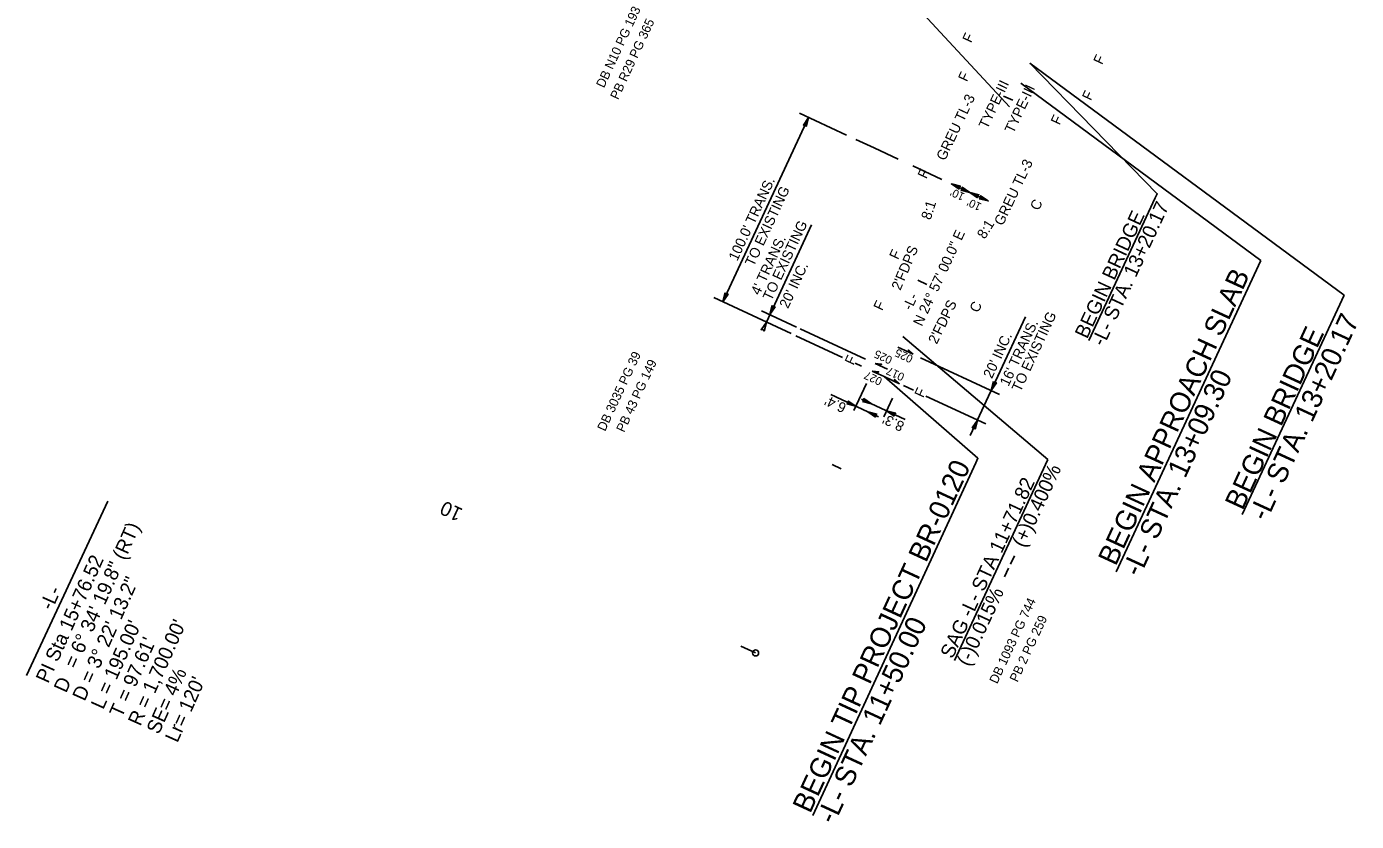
# Model space of a CAD drawing. Extents: x 2532362 to 2533150, y 715234 to 716115.
# Drawn here: x 2532362 to 2533016, y 715234 to 715625 of the extents above; entities that cross this region are included whole.
import ezdxf

# ---------------------------------------------------------------- set-up
doc = ezdxf.new("R2010")
doc.units = 0
for name, color, linetype in [('Default', 7, 'Continuous'), ('Exist Property Deed Book Text', 7, 'Continuous'), ('Old_Level_1', 7, 'Continuous'), ('Prop Dimension', 7, 'Continuous'), ('Prop Dimension Text', 7, 'Continuous'), ('Prop DSN Text', 7, 'Continuous'), ('Prop Horizontal Alignment Curve and Spiral Data', 7, 'Continuous'), ('Prop Horizontal Alignment Direction Label', 7, 'Continuous'), ('Prop Horizontal Alignment Station Label', 7, 'Continuous'), ('Prop Horizontal Alignment Tick Label', 7, 'Continuous'), ('Prop Horizontal Alignment Tick Large', 7, 'Continuous'), ('Prop Horizontal Alignment Tick Small', 7, 'Continuous'), ('Prop Plan Preparation Crest Label', 7, 'Continuous'), ('Prop Plan Preparation Sag Label', 7, 'Continuous'), ('Scratch_Level_0', 7, 'Continuous')]:
    doc.layers.add(name, color=color, linetype=linetype)

msp = doc.modelspace()

# ---------------------------------------------------------------- linework, layer by layer
at = {"layer": 'Old_Level_1'}
for points in [[(2533010.47, 715493), (2532855.87, 715607.16)], [(2532969.52, 715509.99), (2532851.29, 715597.3)], [(2532898.24, 715356.78), (2532969.52, 715509.99)], [(2532960.2, 715384.93), (2533010.47, 715493)]]:
    msp.add_lwpolyline(points, dxfattribs=at)
at = {"layer": 'Prop Dimension'}
for p, q in [((2532704.72, 715489.71), (2532746.93, 715580.45)), ((2532765.6, 715571.76), (2532742.49, 715582.51)), ((2532779.27, 715565.4), (2532770.14, 715569.65)), ((2532790.96, 715559.96), (2532779.27, 715565.4)), ((2532812.48, 715549.95), (2532798.22, 715556.58)), ((2532826.27, 715543.53), (2532817.21, 715547.75)), ((2532835.34, 715539.31), (2532826.27, 715543.53)), ((2532726.15, 715479.74), (2532748.41, 715527.58)), ((2532738.27, 715474.1), (2532700.27, 715491.78)), ((2532740.99, 715477.25), (2532723.76, 715485.26)), ((2532826.43, 715423.81), (2532853.66, 715482.33)), ((2532774.94, 715461.45), (2532742.81, 715476.4)), ((2532763.67, 715462.29), (2532740.67, 715472.99)), ((2532840.84, 715444.11), (2532802.05, 715462.16)), ((2532772.93, 715457.98), (2532769.77, 715459.45)), ((2532775.47, 715449.5), (2532769.25, 715436.13)), ((2532781.36, 715433.09), (2532757.81, 715444.04)), ((2532788.22, 715442.17), (2532783.98, 715433.06)), ((2532798.52, 715446.15), (2532793.62, 715448.42)), ((2532834.09, 715429.6), (2532804.66, 715443.29)), ((2532772.96, 715441.79), (2532794.5, 715431.77))]:
    msp.add_line(p, q, dxfattribs=at)
for points in [[(2532745.81, 715576.02), (2532746.93, 715580.45), (2532744.36, 715576.64), (2532745.32, 715576.84)], [(2532820.96, 715545.15), (2532817.21, 715547.75), (2532821.65, 715546.57), (2532820.79, 715546.08)], [(2532821.85, 715544.65), (2532826.27, 715543.53), (2532822.46, 715546.1), (2532822.66, 715545.14)], [(2532830.03, 715540.93), (2532826.27, 715543.53), (2532830.71, 715542.35), (2532829.85, 715541.86)], [(2532830.91, 715540.43), (2532835.34, 715539.31), (2532831.53, 715541.88), (2532831.73, 715540.92)], [(2532705.84, 715494.14), (2532704.72, 715489.71), (2532707.29, 715493.52), (2532706.32, 715493.32)], [(2532728.96, 715487.79), (2532727.84, 715483.37), (2532730.41, 715487.18), (2532729.44, 715486.98)], [(2532725.03, 715475.31), (2532726.15, 715479.74), (2532723.58, 715475.93), (2532724.54, 715476.13)], [(2532798.42, 715463.84), (2532796.13, 715466.01), (2532796.33, 715464.82)], [(2532778.29, 715455.56), (2532781.44, 715455.23), (2532780.4, 715454.6)], [(2532779.7, 715459.32), (2532782.85, 715458.98), (2532781.81, 715458.36)], [(2532791.58, 715449.38), (2532789.28, 715451.55), (2532789.48, 715450.36)], [(2532837.88, 715450.44), (2532836.76, 715446.01), (2532839.33, 715449.82), (2532838.37, 715449.62)], [(2532773.43, 715440.63), (2532777.85, 715439.51), (2532774.05, 715442.08), (2532774.25, 715441.11)], [(2532765.82, 715439.38), (2532770.24, 715438.26), (2532766.43, 715440.83), (2532766.63, 715439.87)], [(2532779.79, 715432.96), (2532776.04, 715435.56), (2532780.48, 715434.38), (2532779.62, 715433.89)], [(2532789.1, 715433.43), (2532785.34, 715436.03), (2532789.78, 715434.84), (2532788.92, 715434.36)], [(2532828.89, 715427.07), (2532830.01, 715431.5), (2532827.44, 715427.69), (2532828.4, 715427.89)]]:
    msp.add_lwpolyline(points, close=True, dxfattribs=at)
at = {"layer": 'Prop Dimension Text'}
for p, q in [((2532798.42, 715463.84), (2532790.84, 715467.37)), ((2532784.09, 715452.86), (2532778.29, 715455.56)), ((2532785.78, 715456.49), (2532779.7, 715459.32)), ((2532791.58, 715449.38), (2532784.09, 715452.86))]:
    msp.add_line(p, q, dxfattribs=at)
at = {"layer": 'Prop DSN Text'}
msp.add_line((2532829.19, 715410.36), (2532749.07, 715236.8), dxfattribs=at)
msp.add_lwpolyline([(2532829.19, 715410.36), (2532830.27, 715412.69), (2532784.09, 715452.86)], dxfattribs=at)
at = {"layer": 'Prop Horizontal Alignment Direction Label'}
msp.add_line((2532362.11, 715305.81), (2532402.04, 715391.62), dxfattribs=at)
at = {"layer": 'Prop Horizontal Alignment Station Label'}
msp.add_circle((2532720.82, 715316.86), 1.5, dxfattribs=at)
at = {"layer": 'Prop Horizontal Alignment Tick Large'}
msp.add_line((2532720.82, 715316.86), (2532713.56, 715320.24), dxfattribs=at)
at = {"layer": 'Prop Horizontal Alignment Tick Small'}
for p, q in [((2532847.36, 715588.86), (2532842.83, 715590.97)), ((2532805.18, 715498.2), (2532800.65, 715500.31)), ((2532763, 715407.53), (2532758.47, 715409.64))]:
    msp.add_line(p, q, dxfattribs=at)
at = {"layer": 'Prop Plan Preparation Crest Label'}
msp.add_lwpolyline([(2532774.18, 715664.62), (2532773.69, 715663.57), (2532845.86, 715585.65)], dxfattribs=at)
at = {"layer": 'Prop Plan Preparation Sag Label'}
for p, q in [((2532864.69, 715412.1), (2532818.66, 715313.16)), ((2532846.24, 715360.5), (2532848.17, 715364.66)), ((2532845.32, 715358.52), (2532843.38, 715354.36))]:
    msp.add_line(p, q, dxfattribs=at)
msp.add_lwpolyline([(2532864.69, 715412.1), (2532793.29, 715472.65)], dxfattribs=at)
at = {"layer": 'Scratch_Level_0'}
msp.add_line((2532917.54, 715540.88), (2532884.88, 715470.67), dxfattribs=at)
msp.add_lwpolyline([(2532917.54, 715540.88), (2532918.48, 715542.89), (2532855.87, 715607.16)], dxfattribs=at)

# ---------------------------------------------------------------- texts
at = {"layer": 'Default'}
for s, p in [('F', (2532826.91, 715616.81)), ('F', (2532891.33, 715606.1)), ('F', (2532824.8, 715597.69)), ('F', (2532885.79, 715588.42)), ('F', (2532870.38, 715576.39)), ('F', (2532804.86, 715549.89)), ('C', (2532860.19, 715534.25)), ('F', (2532790.92, 715510.13)), ('F', (2532783.13, 715484.99)), ('C', (2532830.4, 715483.98)), ('F', (2532769.01, 715458.13)), ('F', (2532803.32, 715442.1))]:
    msp.add_text(s, height=5, rotation=65.05, dxfattribs=at).set_placement(p)
at = {"layer": 'Exist Property Deed Book Text'}
for s, p in [('DB N10 PG 193', (2532646.22, 715594.66)), ('PB R29 PG 365', (2532653.15, 715588.9)), ('DB 3035 PG 39', (2532646.78, 715425.63)), ('PB 43 PG 149', (2532656.14, 715425.1)), ('DB 1093 PG 744', (2532839.71, 715301.32)), ('PB 2 PG 259', (2532849.7, 715302.14))]:
    msp.add_text(s, height=4.5, rotation=65.05, dxfattribs=at).set_placement(p)
at = {"layer": 'Old_Level_1'}
for s, p in [('BEGIN APPROACH SLAB', (2532898.07, 715359.21)), ('-L- STA. 13+20.17', (2532972.28, 715381.19)), ('BEGIN BRIDGE', (2532960.47, 715386.62)), ('-L- STA. 13+09.30', (2532909.88, 715353.77))]:
    msp.add_text(s, height=10, rotation=65.30119, dxfattribs=at).set_placement(p)
at = {"layer": 'Prop Dimension Text'}
for s, height, rotation, p in [("100.0' TRANS.", 5, 65.05, (2532711.81, 715509.43)), ('TO EXISTING', 5, 65.05, (2532719.93, 715506.74)), ("10'", 4, 155.05, (2532824.16, 715542.84)), ("10'", 4, 155.05, (2532832.42, 715537.88)), ('TO EXISTING', 5, 65.05, (2532728.65, 715489.85)), ("4' TRANS.", 5, 65.05, (2532722.76, 715492.59)), ("20' INC.", 5, 65.05, (2532736.81, 715486.05)), ('TO EXISTING', 5, 65.05, (2532851.18, 715445)), ("16' TRANS.", 5, 65.05, (2532845.29, 715447.74)), ("20' INC.", 5, 65.05, (2532837.13, 715451.54)), ('025', 4, 155.05, (2532788.5, 715462.38)), ('025', 4, 155.05, (2532798.68, 715462.99)), ('027', 4, 155.05, (2532783.54, 715451.9)), ('017', 4, 155.05, (2532794.49, 715454.09)), ("6.4'", 5, 155.05, (2532765.94, 715439.26)), ("8.3'", 5, 155.05, (2532794.46, 715430.12))]:
    msp.add_text(s, height=height, rotation=rotation, dxfattribs=at).set_placement(p)
at = {"layer": 'Prop DSN Text'}
for s, height, rotation, p in [('TYPE-III', 5, 64.62634, (2532834.9, 715574.42)), ('TYPE-III', 5, 64.62634, (2532847.69, 715572.25)), ('GREU TL-3', 5, 64.62634, (2532814.04, 715558.79)), ('GREU TL-3', 5, 64.62634, (2532842.49, 715526.79)), ('8:1', 5, 72.17834, (2532806.92, 715529.68)), ('8:1', 5, 57.92308, (2532833.64, 715520.23)), ("2'FDPS", 5, 66.97981, (2532792.06, 715494.97)), ("2'FDPS", 5, 63.91215, (2532809.99, 715468.49)), ('BEGIN TIP PROJECT BR-0120', 10, 65.21898, (2532747.71, 715237.43)), ('-L- STA. 11+50.00', 10, 65.21898, (2532759.51, 715231.98))]:
    msp.add_text(s, height=height, rotation=rotation, dxfattribs=at).set_placement(p)
at = {"layer": 'Prop Horizontal Alignment Curve and Spiral Data'}
for s, p in [('= 6%%d 34\' 19.8" (RT)', (2532386.54, 715308.65)), ('PI Sta 15+76.52', (2532372.71, 715301.5)), ('D = 3%%d 22\' 13.2"', (2532390.69, 715292.71)), ('-L-', (2532374.6, 715337.39)), ("L = 195.00'", (2532399.81, 715288.63)), ("R = 1,700.00'", (2532418.07, 715280.45)), ("T = 97.61'", (2532408.94, 715284.54)), ('D', (2532381.56, 715296.8)), ('SE= 4%', (2532427.19, 715276.36)), ("Lr= 120'", (2532436.32, 715272.28))]:
    msp.add_text(s, height=7, rotation=65.87387, dxfattribs=at).set_placement(p)
at = {"layer": 'Prop Horizontal Alignment Direction Label'}
for s, p in [('N 24%%d 57\' 00.0" E', (2532802.66, 715477.31)), ('-L-', (2532797.46, 715485.11))]:
    msp.add_text(s, height=5, rotation=65.21898, dxfattribs=at).set_placement(p)
at = {"layer": 'Prop Horizontal Alignment Tick Label'}
msp.add_text('10', height=7, rotation=155.05, dxfattribs=at).set_placement((2532577.22, 715387.53))
at = {"layer": 'Prop Plan Preparation Sag Label'}
for s, p in [('SAG -L- STA 11+71.82', (2532817.75, 715313.58)), ('(-)0.015%         (+)0.400%', (2532825.91, 715309.78))]:
    msp.add_text(s, height=7, rotation=65.05, dxfattribs=at).set_placement(p)
at = {"layer": 'Scratch_Level_0'}
for s, p in [('BEGIN BRIDGE', (2532883.97, 715471.09)), ('-L- STA. 13+20.17', (2532892.13, 715467.3))]:
    msp.add_text(s, height=7, rotation=65.05, dxfattribs=at).set_placement(p)

doc.saveas('drawing.dxf')
